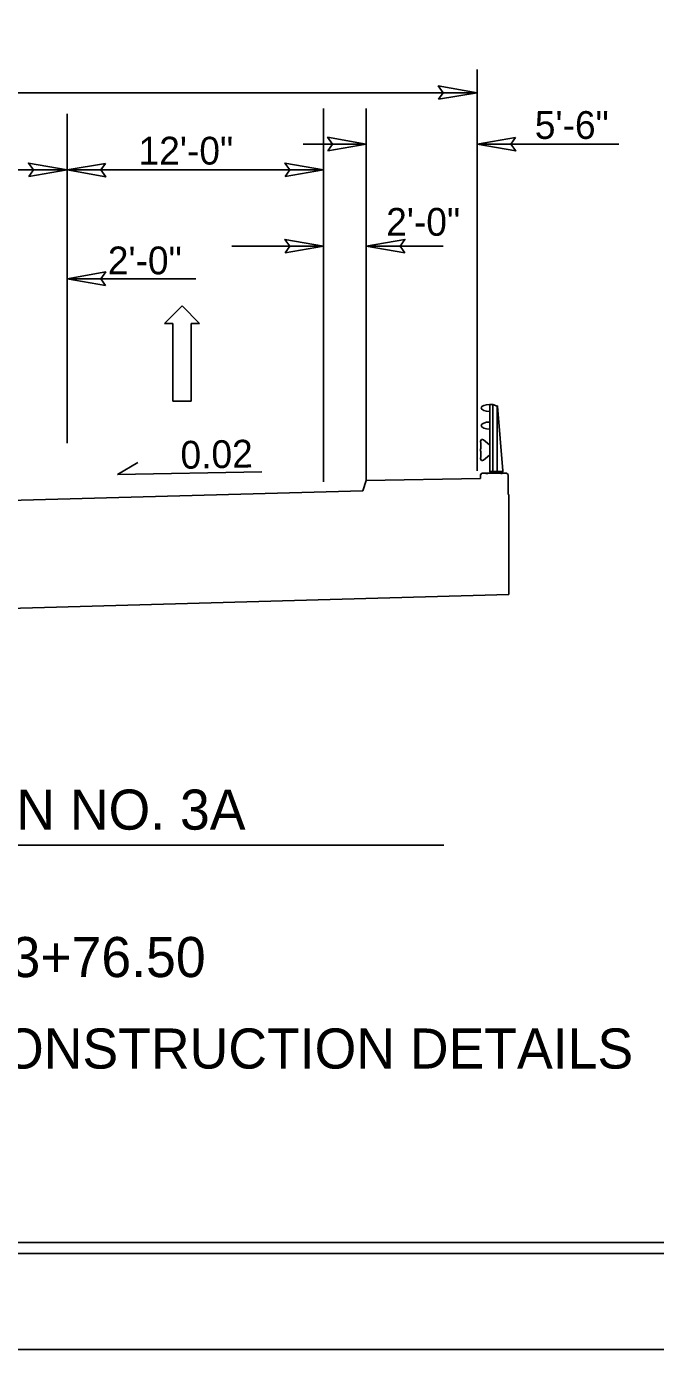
# Model space of a CAD drawing. Extents: x 1904401 to 1905163, y 193929 to 194736.
# Drawn here: x 1904900.4 to 1904929.9, y 194494.2 to 194556.1 of the extents above; entities that cross this region are included whole.
import ezdxf

# ---------------------------------------------------------------- set-up
doc = ezdxf.new("R2010")
doc.units = 0
for name, color, linetype in [('Old_Level_1', 7, 'Continuous'), ('Prop Dimension', 7, 'Continuous'), ('Prop Dimension Text', 7, 'Continuous'), ('Prop Lane Arrow CELL', 7, 'Continuous'), ('Prop Terminator CELL', 7, 'Continuous'), ('Sheet Cutting Line CELL', 7, 'Continuous'), ('Sheet Plot Border Inside CELL', 7, 'Continuous'), ('Sheet Plot Border Outside CELL', 7, 'Continuous'), ('Sheet Typical CELL', 7, 'Continuous'), ('Typical Arrow Superelevation CELL', 7, 'Continuous'), ('Typical Pavement Slope CELL', 7, 'Continuous'), ('Typical Sidewalk and Rail CELL', 7, 'Continuous')]:
    doc.layers.add(name, color=color, linetype=linetype)

msp = doc.modelspace()

# ---------------------------------------------------------------- linework, layer by layer
at = {"layer": 'Old_Level_1'}
msp.add_line((1904862.045, 194517.787), (1904919.951, 194517.787), dxfattribs=at)
at = {"layer": 'Prop Dimension'}
for p, q in [((1904921.506, 194554.069), (1904921.506, 194535.301)), ((1904921.506, 194552.985), (1904865.647, 194552.985)), ((1904902.326, 194552.003), (1904902.326, 194536.587)), ((1904914.326, 194552.244), (1904914.326, 194534.789)), ((1904916.326, 194552.244), (1904916.326, 194534.815)), ((1904913.371, 194550.58), (1904916.326, 194550.58)), ((1904921.506, 194550.58), (1904928.148, 194550.58)), ((1904902.326, 194549.369), (1904893.267, 194549.369)), ((1904914.326, 194549.369), (1904902.326, 194549.369)), ((1904914.326, 194549.869), (1904914.326, 194535.413)), ((1904914.326, 194549.869), (1904914.326, 194535.413)), ((1904914.326, 194549.369), (1904914.326, 194534.918)), ((1904914.326, 194545.804), (1904910.026, 194545.804)), ((1904916.326, 194545.804), (1904919.919, 194545.804)), ((1904902.326, 194544.281), (1904908.349, 194544.281)), ((1904916.326, 194541.759), (1904916.326, 194534.815))]:
    msp.add_line(p, q, dxfattribs=at)
at = {"layer": 'Prop Lane Arrow CELL'}
for p, q in [((1904907.711, 194543.009), (1904906.881, 194542.192)), ((1904908.516, 194542.192), (1904907.711, 194543.009)), ((1904906.881, 194542.192), (1904907.271, 194542.192)), ((1904907.271, 194542.192), (1904907.271, 194538.561)), ((1904908.126, 194538.561), (1904908.126, 194542.192)), ((1904908.126, 194542.192), (1904908.516, 194542.192)), ((1904907.271, 194538.561), (1904908.126, 194538.561))]:
    msp.add_line(p, q, dxfattribs=at)
at = {"layer": 'Prop Terminator CELL'}
for points in [[(1904919.706, 194552.675), (1904921.506, 194552.985), (1904919.696, 194553.305), (1904919.926, 194552.985)], [(1904914.526, 194550.27), (1904916.326, 194550.58), (1904914.516, 194550.9), (1904914.746, 194550.58)], [(1904923.306, 194550.89), (1904921.506, 194550.58), (1904923.316, 194550.26), (1904923.086, 194550.58)], [(1904900.526, 194549.059), (1904902.326, 194549.369), (1904900.516, 194549.689), (1904900.746, 194549.369)], [(1904904.126, 194549.679), (1904902.326, 194549.369), (1904904.136, 194549.049), (1904903.906, 194549.369)], [(1904912.526, 194549.059), (1904914.326, 194549.369), (1904912.516, 194549.689), (1904912.746, 194549.369)], [(1904912.526, 194545.494), (1904914.326, 194545.804), (1904912.516, 194546.124), (1904912.746, 194545.804)], [(1904918.126, 194545.494), (1904916.326, 194545.804), (1904918.136, 194546.124), (1904917.906, 194545.804)], [(1904904.126, 194543.971), (1904902.326, 194544.281), (1904904.136, 194544.601), (1904903.906, 194544.281)]]:
    msp.add_lwpolyline(points, close=True, dxfattribs=at)
at = {"layer": 'Sheet Cutting Line CELL'}
msp.add_line((1904710.692, 194494.195), (1905047.492, 194494.195), dxfattribs=at)
at = {"layer": 'Sheet Plot Border Inside CELL'}
msp.add_lwpolyline([(1905046.592, 194709.705), (1904713.292, 194709.705), (1904713.292, 194498.685), (1905046.592, 194498.685)], close=True, dxfattribs=at)
at = {"layer": 'Sheet Plot Border Outside CELL'}
msp.add_lwpolyline([(1905047.492, 194714.195), (1904710.692, 194714.195), (1904710.692, 194494.195), (1905047.492, 194494.195)], close=True, dxfattribs=at)
at = {"layer": 'Sheet Typical CELL'}
msp.add_lwpolyline([(1905044.092, 194709.195), (1904744.092, 194709.195), (1904744.092, 194499.195), (1905044.092, 194499.195)], close=True, dxfattribs=at)
at = {"layer": 'Typical Arrow Superelevation CELL'}
for q in [(1904905.629, 194535.688), (1904911.438, 194535.255)]:
    msp.add_line((1904904.689, 194535.12), q, dxfattribs=at)
at = {"layer": 'Typical Pavement Slope CELL'}
msp.add_line((1904916.166, 194534.368), (1904894.087, 194533.761), dxfattribs=at)
at = {"layer": 'Typical Sidewalk and Rail CELL'}
for p, q in [((1904921.687, 194536.589), (1904921.677, 194536.674)), ((1904922.089, 194536.518), (1904921.811, 194536.747)), ((1904921.676, 194536.311), (1904921.676, 194536.271)), ((1904921.676, 194536.231), (1904921.676, 194536.271)), ((1904921.687, 194535.952), (1904921.677, 194535.867)), ((1904922.089, 194536.023), (1904921.811, 194535.795)), ((1904921.665, 194535.115), (1904921.738, 194535.188)), ((1904921.665, 194534.938), (1904921.665, 194535.115)), ((1904921.738, 194535.188), (1904922.892, 194535.188)), ((1904921.924, 194535.18), (1904922.006, 194535.18)), ((1904922.615, 194535.18), (1904922.676, 194535.18)), ((1904922.957, 194535.124), (1904922.892, 194535.188)), ((1904922.957, 194535.124), (1904922.957, 194534.195)), ((1904916.166, 194534.368), (1904916.326, 194534.849)), ((1904921.665, 194534.938), (1904916.326, 194534.849)), ((1904922.957, 194534.195), (1904922.999, 194534.195)), ((1904922.999, 194529.508), (1904922.999, 194534.195)), ((1904922.999, 194529.508), (1904864.154, 194527.892))]:
    msp.add_line(p, q, dxfattribs=at)
msp.add_lwpolyline([(1904922.099, 194538.405), (1904922.243, 194538.405), (1904922.45, 194538.322), (1904922.47, 194538.322), (1904922.718, 194535.291), (1904922.718, 194535.26), (1904922.099, 194535.26), (1904922.099, 194538.405), (1904922.243, 194538.405), (1904922.243, 194535.26), (1904922.45, 194535.26), (1904922.45, 194538.322)], dxfattribs=at)
for centre, radius, start, end in [((1904921.759, 194536.683), 0.0824, 50.55682, 186.06715), ((1904921.412, 194536.399), 0.279, 341.41786, 354.52653), ((1904921.93, 194536.489), 0.247, 173.17998, 190.79491), ((1904921.459, 194536.562), 0.23, 349.20135, 6.82002), ((1904921.461, 194536.4), 0.23, 353.17998, 10.79865), ((1904921.412, 194536.142), 0.279, 5.47347, 18.58214), ((1904921.759, 194535.858), 0.0824, 173.93285, 309.44318), ((1904921.93, 194536.052), 0.247, 169.20509, 186.82002), ((1904921.459, 194535.979), 0.23, 353.17998, 10.79865), ((1904921.461, 194536.141), 0.23, 349.20135, 6.82002)]:
    msp.add_arc(centre, radius, start, end, dxfattribs=at)
for centre, start_param, end_param in [((1904922.099, 194538.24), 4.712389, 6.283185), ((1904922.099, 194538.24), 0, 1.570796), ((1904922.099, 194537.415), 4.712389, 6.283185), ((1904922.099, 194537.415), 0, 1.570796)]:
    msp.add_ellipse(centre, major_axis=(-0.392, 0), ratio=0.42124, start_param=start_param, end_param=end_param, dxfattribs=at)

# ---------------------------------------------------------------- texts
at = {"layer": 'Old_Level_1'}
msp.add_text('BRIDGE TYPICAL SECTION NO. 3A', height=1.875, dxfattribs=at).set_placement((1904869.155, 194518.513))
at = {"layer": 'Prop Dimension'}
for p in [(1904917.255, 194546.293), (1904904.229, 194544.489)]:
    msp.add_text('2\'-0"', height=1.3, dxfattribs=at).set_placement(p)
at = {"layer": 'Prop Dimension Text'}
for s, p in [('5\'-6"', (1904924.211, 194550.823)), ('12\'-0"', (1904905.667, 194549.623))]:
    msp.add_text(s, height=1.3, dxfattribs=at).set_placement(p)
msp.add_text('0.02', height=1.3, rotation=1.1462, dxfattribs=at).set_placement((1904907.643, 194535.39))
at = {"layer": 'Prop Lane Arrow CELL'}
for s, p in [('-L- STA. 31+71.00 TO 33+76.50', (1904872.848, 194511.616)), ('SEE STRUCTURE PLANS FOR CONSTRUCTION DETAILS', (1904860.691, 194507.338))]:
    msp.add_text(s, height=1.875, dxfattribs=at).set_placement(p)

doc.saveas('drawing.dxf')
